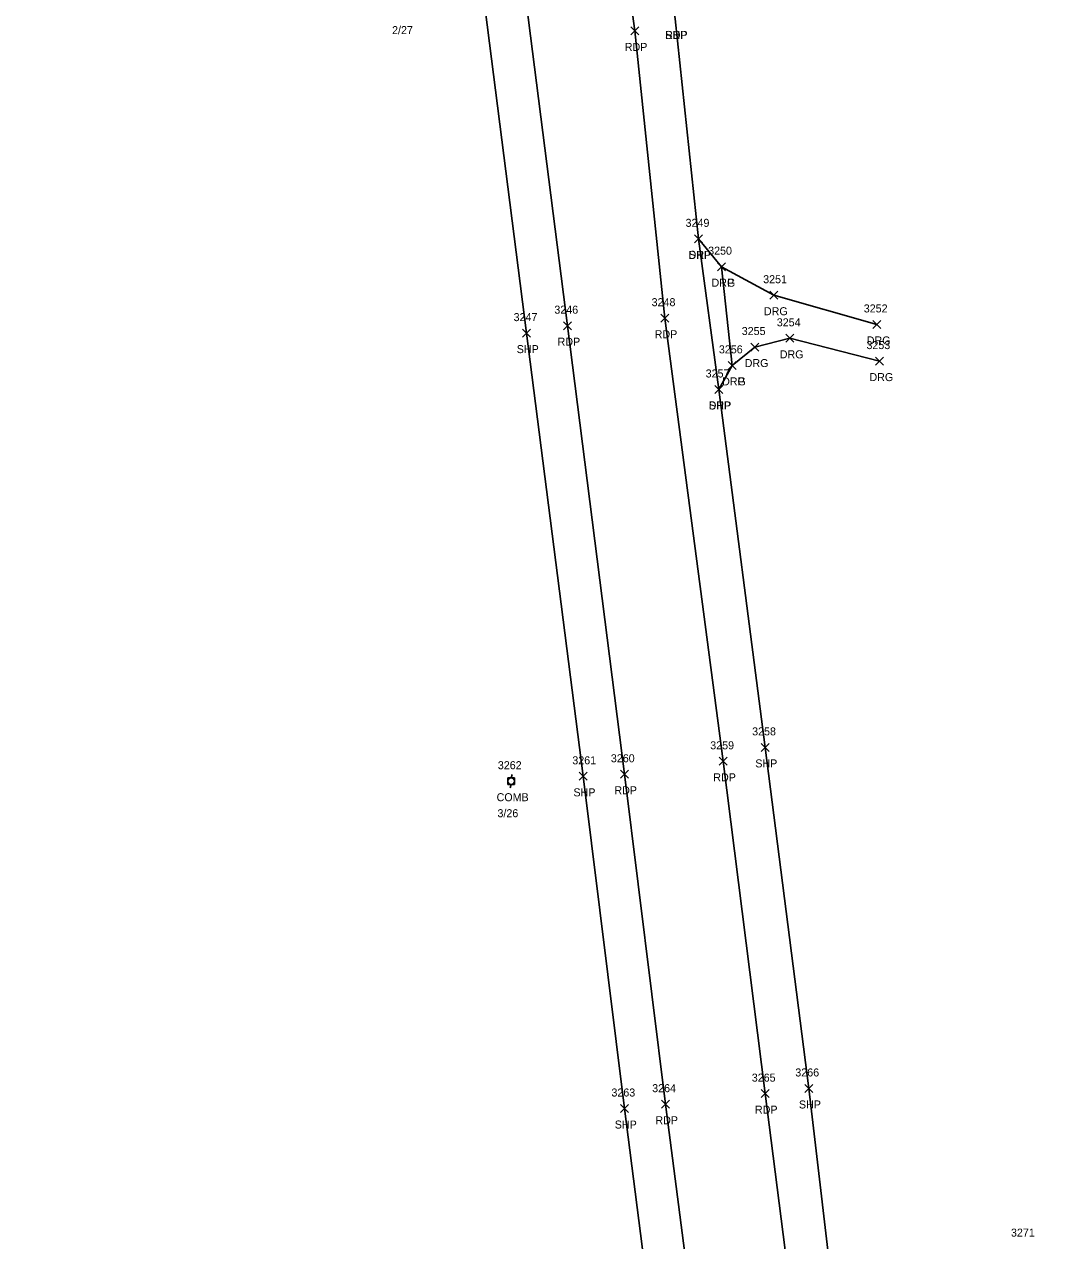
# Model space of a CAD drawing. Extents: x 1443071 to 1445292, y 614024 to 622563.
# Drawn here: x 1444280.5 to 1444535.7, y 616018.1 to 616322 of the extents above; entities that cross this region are included whole.
import ezdxf

# ---------------------------------------------------------------- set-up
doc = ezdxf.new("R2010")
doc.units = 0
for name, color, linetype in [('P_A', 7, 'Continuous'), ('P_I', 7, 'Continuous'), ('P_TIC', 7, 'Continuous'), ('PET', 7, 'Continuous'), ('PSP', 7, 'Continuous'), ('R_A', 7, 'Continuous'), ('R_I', 7, 'Continuous'), ('R_TIC', 7, 'Continuous'), ('RDG', 7, 'Continuous'), ('RDP', 7, 'Continuous'), ('U_A', 7, 'Continuous'), ('U_C', 7, 'Continuous'), ('U_I', 7, 'Continuous'), ('UP', 7, 'Continuous')]:
    doc.layers.add(name, color=color, linetype=linetype)

msp = doc.modelspace()

# ---------------------------------------------------------------- linework, layer by layer
at = {"layer": 'P_TIC'}
for points in [[(1444432.04, 616319.39), (1444434.04, 616321.39)], [(1444434.04, 616319.39), (1444432.04, 616321.39)], [(1444447.99, 616267.44), (1444449.99, 616269.44)], [(1444449.99, 616267.44), (1444447.99, 616269.44)], [(1444439.5, 616247.61), (1444441.5, 616249.61)], [(1444441.5, 616247.61), (1444439.5, 616249.61)], [(1444415.25, 616245.74), (1444417.25, 616247.74)], [(1444417.25, 616245.74), (1444415.25, 616247.74)], [(1444405.01, 616243.88), (1444407.01, 616245.88)], [(1444407.01, 616243.88), (1444405.01, 616245.88)], [(1444453, 616229.8), (1444455, 616231.8)], [(1444455, 616229.8), (1444453, 616231.8)], [(1444464.61, 616140.36), (1444466.61, 616142.36)], [(1444466.61, 616140.36), (1444464.61, 616142.36)], [(1444454.15, 616136.88), (1444456.15, 616138.88)], [(1444456.15, 616136.88), (1444454.15, 616138.88)], [(1444419.16, 616133.13), (1444421.16, 616135.13)], [(1444421.16, 616133.13), (1444419.16, 616135.13)], [(1444429.45, 616133.64), (1444431.45, 616135.64)], [(1444431.45, 616133.64), (1444429.45, 616135.64)], [(1444464.57, 616053.84), (1444466.57, 616055.84)], [(1444466.57, 616053.84), (1444464.57, 616055.84)], [(1444475.5, 616055.13), (1444477.5, 616057.13)], [(1444477.5, 616055.13), (1444475.5, 616057.13)], [(1444429.49, 616050.12), (1444431.49, 616052.12)], [(1444431.49, 616050.12), (1444429.49, 616052.12)], [(1444439.68, 616051.2), (1444441.68, 616053.2)], [(1444441.68, 616051.2), (1444439.68, 616053.2)]]:
    msp.add_lwpolyline(points, dxfattribs=at)
at = {"layer": 'PET'}
for points in [[(1444290.04, 617226.49), (1444293.29, 617200.68), (1444305.86, 617102.26), (1444318.1, 617012.36), (1444328.61, 616929.53), (1444340.48, 616832.7), (1444349.36, 616766.46), (1444359.48, 616687.73), (1444375.76, 616559.26), (1444386.72, 616474.82), (1444392.98, 616424.11), (1444399.64, 616374.74), (1444405.35, 616331.68), (1444416.25, 616246.74), (1444430.45, 616134.64), (1444440.68, 616052.2), (1444460.71, 615897.87), (1444469.48, 615825.17), (1444479.32, 615749.85), (1444490.82, 615663.43), (1444501.1, 615593.99)], [(1444314.9, 617227.6), (1444331.28, 617099.37), (1444342.74, 617014.98), (1444353.45, 616933.43), (1444365.99, 616834.42), (1444373.87, 616769.68), (1444384.25, 616690.54), (1444399.86, 616561.36), (1444411.32, 616477.78), (1444418.43, 616426.72), (1444433.04, 616320.39), (1444440.5, 616248.61), (1444455.15, 616137.88), (1444465.57, 616054.84), (1444485.3, 615900.9), (1444494.14, 615826.26), (1444503.74, 615751.94), (1444515.41, 615666.64), (1444525.64, 615597.72)]]:
    msp.add_lwpolyline(points, dxfattribs=at)
at = {"layer": 'PSP'}
for points in [[(1444325.72, 617229.34), (1444331.18, 617190.03), (1444341.63, 617111.11), (1444353.65, 617016.1), (1444364.55, 616934.22), (1444377.14, 616835.48), (1444385.64, 616770.75), (1444395.97, 616692.96), (1444412.43, 616562.03), (1444423.01, 616481.11), (1444430.88, 616420.51), (1444443.11, 616323.39), (1444448.99, 616268.44), (1444454, 616230.8), (1444465.61, 616141.36), (1444476.5, 616056.13), (1444483.28, 615998.72), (1444489.46, 615946.55), (1444495.54, 615902.14), (1444505.18, 615827.19), (1444514.81, 615753.2), (1444525.85, 615667.7), (1444535.69, 615600.77)], [(1444280.5, 617226.12), (1444283.66, 617200.61), (1444293.17, 617127.11), (1444296.38, 617100.83), (1444308.28, 617010.91), (1444318.74, 616928.98), (1444325.56, 616872.02), (1444335.05, 616795.34), (1444338.72, 616765.27), (1444349.45, 616686.56), (1444353.22, 616653.3), (1444364.91, 616559.25), (1444375.85, 616473.62), (1444383.24, 616422.24), (1444388.01, 616382.64), (1444395.12, 616329.81), (1444406.01, 616244.88), (1444420.16, 616134.13), (1444430.49, 616051.12), (1444450.17, 615896.86), (1444459.96, 615823.48), (1444469.66, 615749), (1444481.34, 615661.86), (1444491.6, 615592.34)]]:
    msp.add_lwpolyline(points, dxfattribs=at)
at = {"layer": 'R_TIC'}
for points in [[(1444447.99, 616267.44), (1444449.99, 616269.44)], [(1444449.99, 616267.44), (1444447.99, 616269.44)], [(1444453.71, 616260.48), (1444455.71, 616262.48)], [(1444455.71, 616260.48), (1444453.71, 616262.48)], [(1444453.71, 616260.48), (1444455.71, 616262.48)], [(1444455.71, 616260.48), (1444453.71, 616262.48)], [(1444466.81, 616253.35), (1444468.81, 616255.35)], [(1444468.81, 616253.35), (1444466.81, 616255.35)], [(1444492.5, 616246.05), (1444494.5, 616248.05)], [(1444494.5, 616246.05), (1444492.5, 616248.05)], [(1444470.77, 616242.58), (1444472.77, 616244.58)], [(1444472.77, 616242.58), (1444470.77, 616244.58)], [(1444462.01, 616240.4), (1444464.01, 616242.4)], [(1444464.01, 616240.4), (1444462.01, 616242.4)], [(1444456.35, 616235.82), (1444458.35, 616237.82)], [(1444458.35, 616235.82), (1444456.35, 616237.82)], [(1444456.35, 616235.82), (1444458.35, 616237.82)], [(1444458.35, 616235.82), (1444456.35, 616237.82)], [(1444493.17, 616236.89), (1444495.17, 616238.89)], [(1444495.17, 616236.89), (1444493.17, 616238.89)], [(1444453, 616229.8), (1444455, 616231.8)], [(1444455, 616229.8), (1444453, 616231.8)]]:
    msp.add_lwpolyline(points, dxfattribs=at)
at = {"layer": 'RDG'}
for points in [[(1444454.71, 616261.48), (1444467.81, 616254.35), (1444493.5, 616247.05)], [(1444494.17, 616237.89), (1444471.77, 616243.58), (1444463.01, 616241.4), (1444457.35, 616236.82)]]:
    msp.add_lwpolyline(points, dxfattribs=at)
at = {"layer": 'RDP'}
msp.add_lwpolyline([(1444448.99, 616268.44), (1444454.71, 616261.48), (1444457.35, 616236.82), (1444454, 616230.8)], dxfattribs=at)
at = {"layer": 'UP'}
for p, q in [((1444402.37, 616134.58), (1444402.12, 616133.74)), ((1444401.28, 616132.08), (1444401.28, 616133.74)), ((1444401.28, 616133.74), (1444402.95, 616133.74)), ((1444402.95, 616132.08), (1444401.28, 616132.08)), ((1444401.87, 616131.24), (1444402.12, 616132.08)), ((1444402.12, 616132.91), (1444402.12, 616132.91)), ((1444402.95, 616133.74), (1444402.95, 616132.08))]:
    msp.add_line(p, q, dxfattribs=at)
msp.add_circle((1444402.12, 616132.91), 0.833, dxfattribs=at)

# ---------------------------------------------------------------- texts
at = {"layer": 'P_A'}
for s, p in [('SHP', (1444440.64, 616318.39)), ('RDP', (1444440.59, 616318.39)), ('RDP', (1444430.53, 616315.39)), ('SHP', (1444446.53, 616263.44)), ('RDP', (1444413.74, 616241.74)), ('RDP', (1444437.99, 616243.61)), ('SHP', (1444403.54, 616239.88)), ('SHP', (1444451.54, 616225.8)), ('SHP', (1444463.14, 616136.36)), ('RDP', (1444452.64, 616132.88)), ('SHP', (1444417.7, 616129.13)), ('RDP', (1444427.93, 616129.64)), ('SHP', (1444474.04, 616051.13)), ('RDP', (1444438.17, 616047.2)), ('RDP', (1444463.05, 616049.84)), ('SHP', (1444428.03, 616046.12))]:
    msp.add_text(s, height=2, dxfattribs=at).set_placement(p)
at = {"layer": 'P_I'}
for s, p in [('3249', (1444445.72, 616271.44)), ('3248', (1444437.24, 616251.61)), ('3247', (1444402.75, 616247.88)), ('3246', (1444412.93, 616249.74)), ('3257', (1444450.74, 616233.8)), ('3258', (1444462.35, 616144.36)), ('3259', (1444451.88, 616140.88)), ('3261', (1444417.42, 616137.13)), ('3260', (1444427.05, 616137.64)), ('3265', (1444462.26, 616057.84)), ('3266', (1444473.14, 616059.13)), ('3263', (1444427.19, 616054.12)), ('3264', (1444437.38, 616055.2))]:
    msp.add_text(s, height=2, dxfattribs=at).set_placement(p)
at = {"layer": 'R_A'}
for s, p in [('DRP', (1444446.48, 616263.44)), ('DRG', (1444452.2, 616256.48)), ('DRP', (1444452.2, 616256.48)), ('DRG', (1444465.29, 616249.35)), ('DRG', (1444490.99, 616242.05)), ('DRG', (1444469.25, 616238.58)), ('DRG', (1444460.49, 616236.4)), ('DRG', (1444491.66, 616232.89)), ('DRG', (1444454.84, 616231.82)), ('DRP', (1444454.84, 616231.82)), ('DRP', (1444451.49, 616225.8))]:
    msp.add_text(s, height=2, dxfattribs=at).set_placement(p)
at = {"layer": 'R_I'}
for s, p in [('3249', (1444445.72, 616271.44)), ('3250', (1444451.36, 616264.48)), ('3250', (1444451.36, 616264.48)), ('3251', (1444465.11, 616257.35)), ('3252', (1444490.24, 616250.05)), ('3254', (1444468.51, 616246.58)), ('3255', (1444459.75, 616244.4)), ('3256', (1444454.04, 616239.82)), ('3256', (1444454.04, 616239.82)), ('3253', (1444490.91, 616240.89)), ('3257', (1444450.74, 616233.8)), ('3271', (1444527.02, 616019.11))]:
    msp.add_text(s, height=2, dxfattribs=at).set_placement(p)
at = {"layer": 'U_A'}
msp.add_text('COMB', height=2, dxfattribs=at).set_placement((1444398.5, 616127.91))
at = {"layer": 'U_C'}
for s, p in [('2/27', (1444372.38, 616319.59)), ('3/26', (1444398.72, 616123.91))]:
    msp.add_text(s, height=2, dxfattribs=at).set_placement(p)
at = {"layer": 'U_I'}
msp.add_text('3262', height=2, dxfattribs=at).set_placement((1444398.81, 616135.91))

doc.saveas('drawing.dxf')
